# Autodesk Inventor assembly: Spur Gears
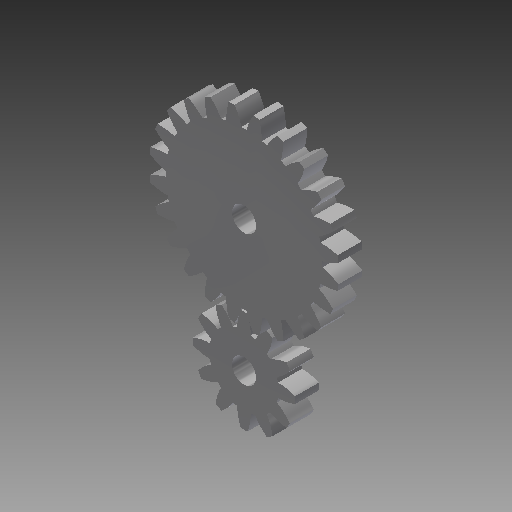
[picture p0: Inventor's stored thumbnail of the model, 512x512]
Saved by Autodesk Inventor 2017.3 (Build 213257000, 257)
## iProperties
ClientObjectVersion: 1
Created: 2020-03
Part Number: Spur Gears
Document SubType Name: Assembly
Designer: Tim_G
Categories: <?xml version="1.0" encoding="UTF-16"?> <MemberInstance><Categories><FamilyTemplate/><ParamToTemplateMap><ParamToTemplate><ParamToTemplate CategoryParameter="//
Author: Tim_G
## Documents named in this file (3)
- C:\Users\Tim_G\OneDrive - McMaster University\Documents\Documents\Books\McMaster First Year Courses\Winter Engineering 1C03\Project\Project Files (Prosthetic Frame Assembly)\Hand Assembly\Design Accelerator\Spur Gears2.iam
- C:\Users\Tim_G\OneDrive - McMaster University\Documents\Documents\Books\McMaster First Year Courses\Winter Engineering 1C03\Project\Project Files (Prosthetic Frame Assembly)\Hand Assembly\Design Accelerator\Spur Gear12.ipt
- C:\Users\Tim_G\OneDrive - McMaster University\Documents\Documents\Books\McMaster First Year Courses\Winter Engineering 1C03\Project\Project Files (Prosthetic Frame Assembly)\Hand Assembly\Design Accelerator\Spur Gear22.ipt
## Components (2 placed, 2 different names)
1. Spur Gear1:1 — Rotation:1
2. Spur Gear2:1 — Rotation:1
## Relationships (1: RelateRotation 1)
- Rotation:1 [RelateRotation]: Spur Gear1:1 ↔ Spur Gear2:1
